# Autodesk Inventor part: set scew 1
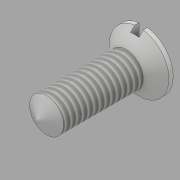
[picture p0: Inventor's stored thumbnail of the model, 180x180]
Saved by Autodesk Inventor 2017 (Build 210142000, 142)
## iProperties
Created: 2016-06
Part Number: set scew 1
Material: Generic
Document SubType Name: Modeling
Designer: CADCIM
Density: 1 g/cm^3
Appearance: Default
Author: CADCIM
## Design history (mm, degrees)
sketch "Sketch1"
  geometry: C1 r 3 at (0, 0); 1 further point
  constraints: 1 centre point, 1 coincident
  dimensions: "d0" = 6 diameter of C1
extrude "Extrusion1" new body sketch "Sketch1" distance "d1" = 14; taper "d2" = 0 deg
sketch "Sketch2"
  geometry: L1 (14, -3)-(14, 3) reference; L2 (14, 0)-(14, -3); L3 (14, -3)-(17, -6); L4 (17, -6)-(17, 0); L5 (17, 0)-(14, 0); 1 further point
  constraints: 8 end point, 2 vertical, 1 midpoint, 1 perpendicular
  dimensions: "d4" = 3 distance of L2.start L2.end; "d5" = 6 distance of L4.end L3.end; "d6" = 3 distance from line of L1.start L4
revolve "Revolution1" sketch "Sketch2" stored, may be unused: angle "d7" = 90 deg
sketch "Sketch3"
  geometry: C1 r 5.25 at (0, 0); 1 further point
  constraints: 1 centre point, 1 coincident
  dimensions: "d8" = 10.5 diameter of C1
extrude "Extrusion2" sketch "Sketch3" distance "d9" = 26.75; taper "d10" = 0 deg
sketch "Sketch4"
  geometry: L1 (-0.75, 8.347)-(0.75, 8.347); L2 (0.75, 8.347)-(0.75, -8.125); L3 (0.75, -8.125)-(-0.75, -8.125); L4 (-0.75, -8.125)-(-0.75, 8.347); L5 (0, 0)-(0, 6.165)
  constraints: 10 end point, 3 parallel, 1 horizontal, 1 perpendicular, 1 other
  dimensions: "d11" = 1.5 distance of L1.start L1.end
extrude "Extrusion3" cut sketch "Sketch4" distance "d12" = 1.5; taper "d13" = 0 deg
sketch "Sketch5"
  geometry: L1 (0, 0)-(0, 3); L2 (0, 3)-(-1.732, 0); L3 (-1.732, 0)-(0, 0); L4 (0, 3)-(0, -3) reference; 1 further point
  constraints: 6 end point, 2 midpoint, 1 perpendicular, 1 point on line, 1 vertical
  dimensions: "d21" = 60 deg angle of L2 L3; "d22" = 3 distance of L1.start L1.end
thread "Thread2" dims "d19" = 10, "d20" = 0
revolve "Revolution3" stored, may be unused: angle "d23" = 90 deg
body "Solid1"
